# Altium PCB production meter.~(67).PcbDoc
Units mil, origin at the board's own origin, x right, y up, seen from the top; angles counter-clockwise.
Board outline 4724.41 x 1338.58 mil, 2 copper layers (Top Layer, Bottom Layer); 57 components, 53 nets, 214 pads, 21 vias.
Unrouted connection lines stored in the file: 27.
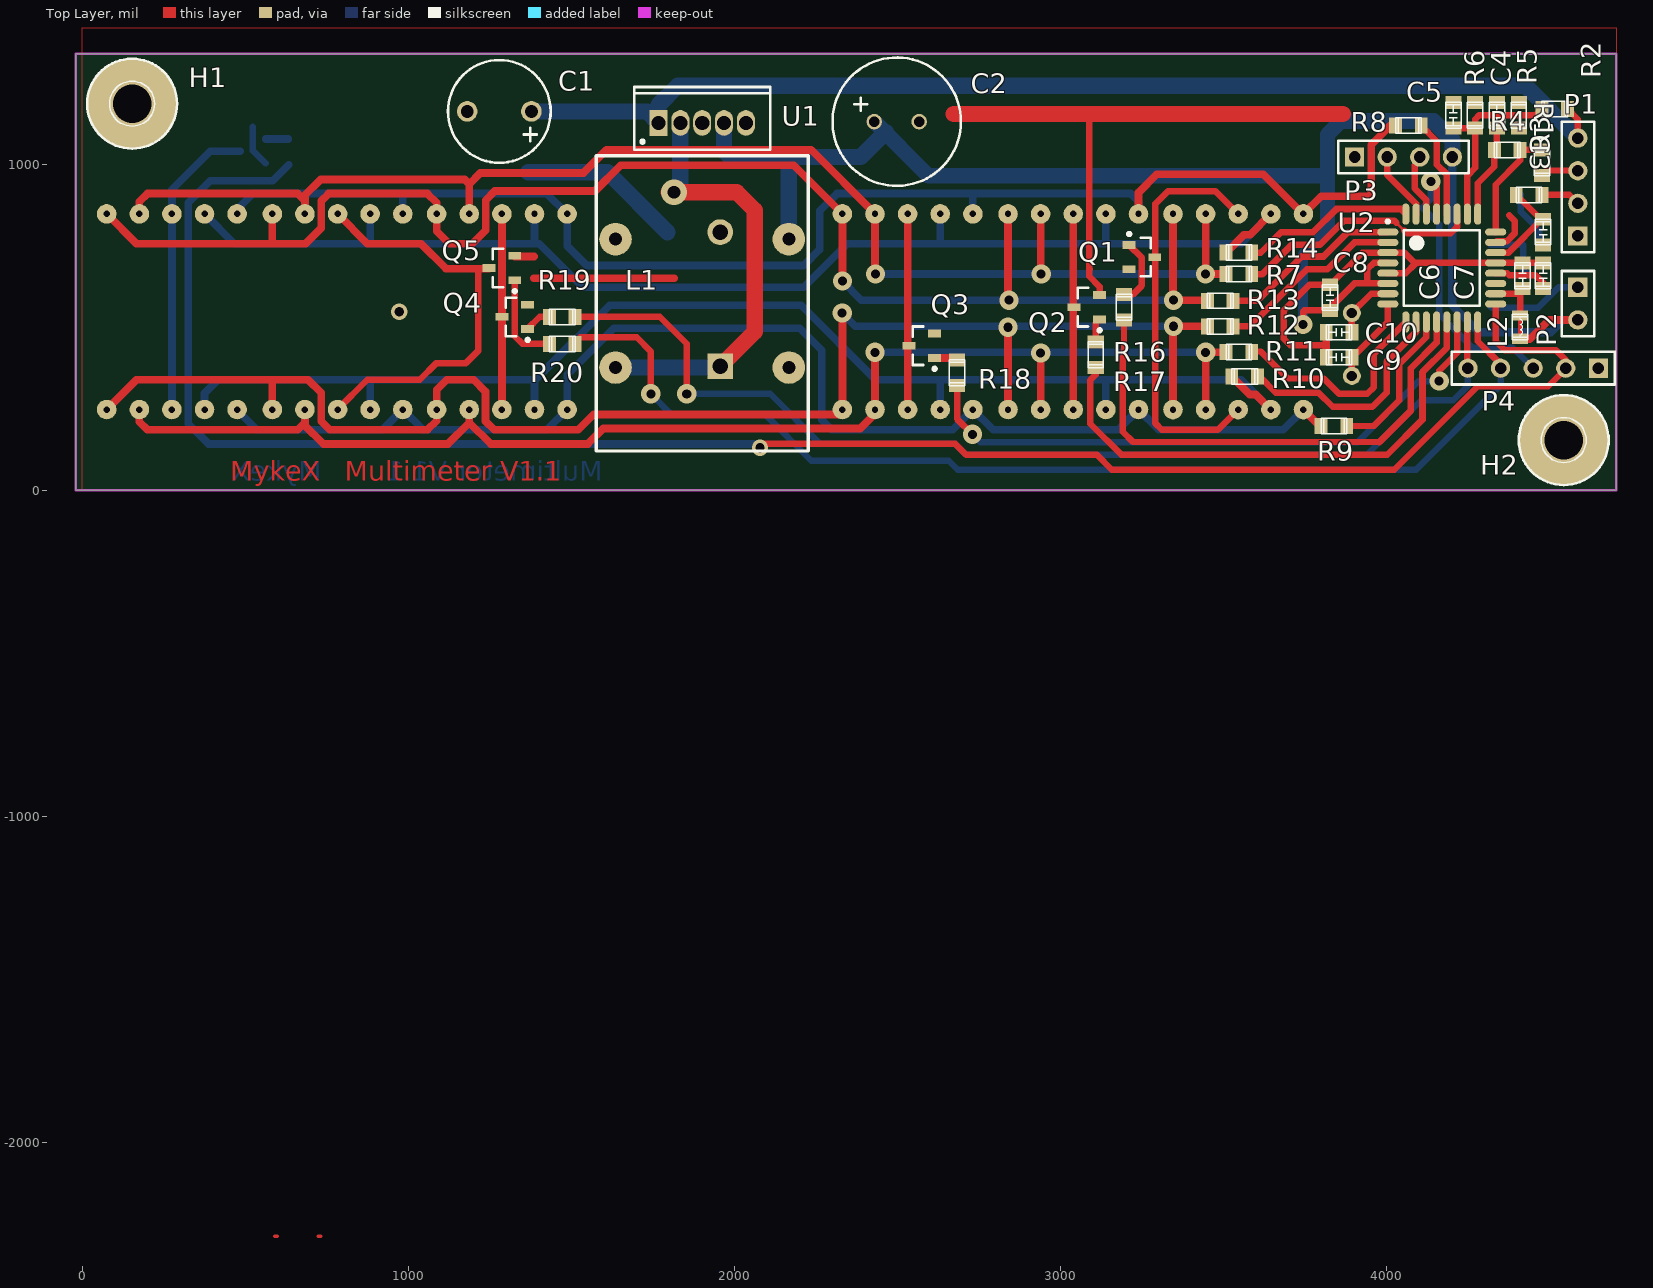
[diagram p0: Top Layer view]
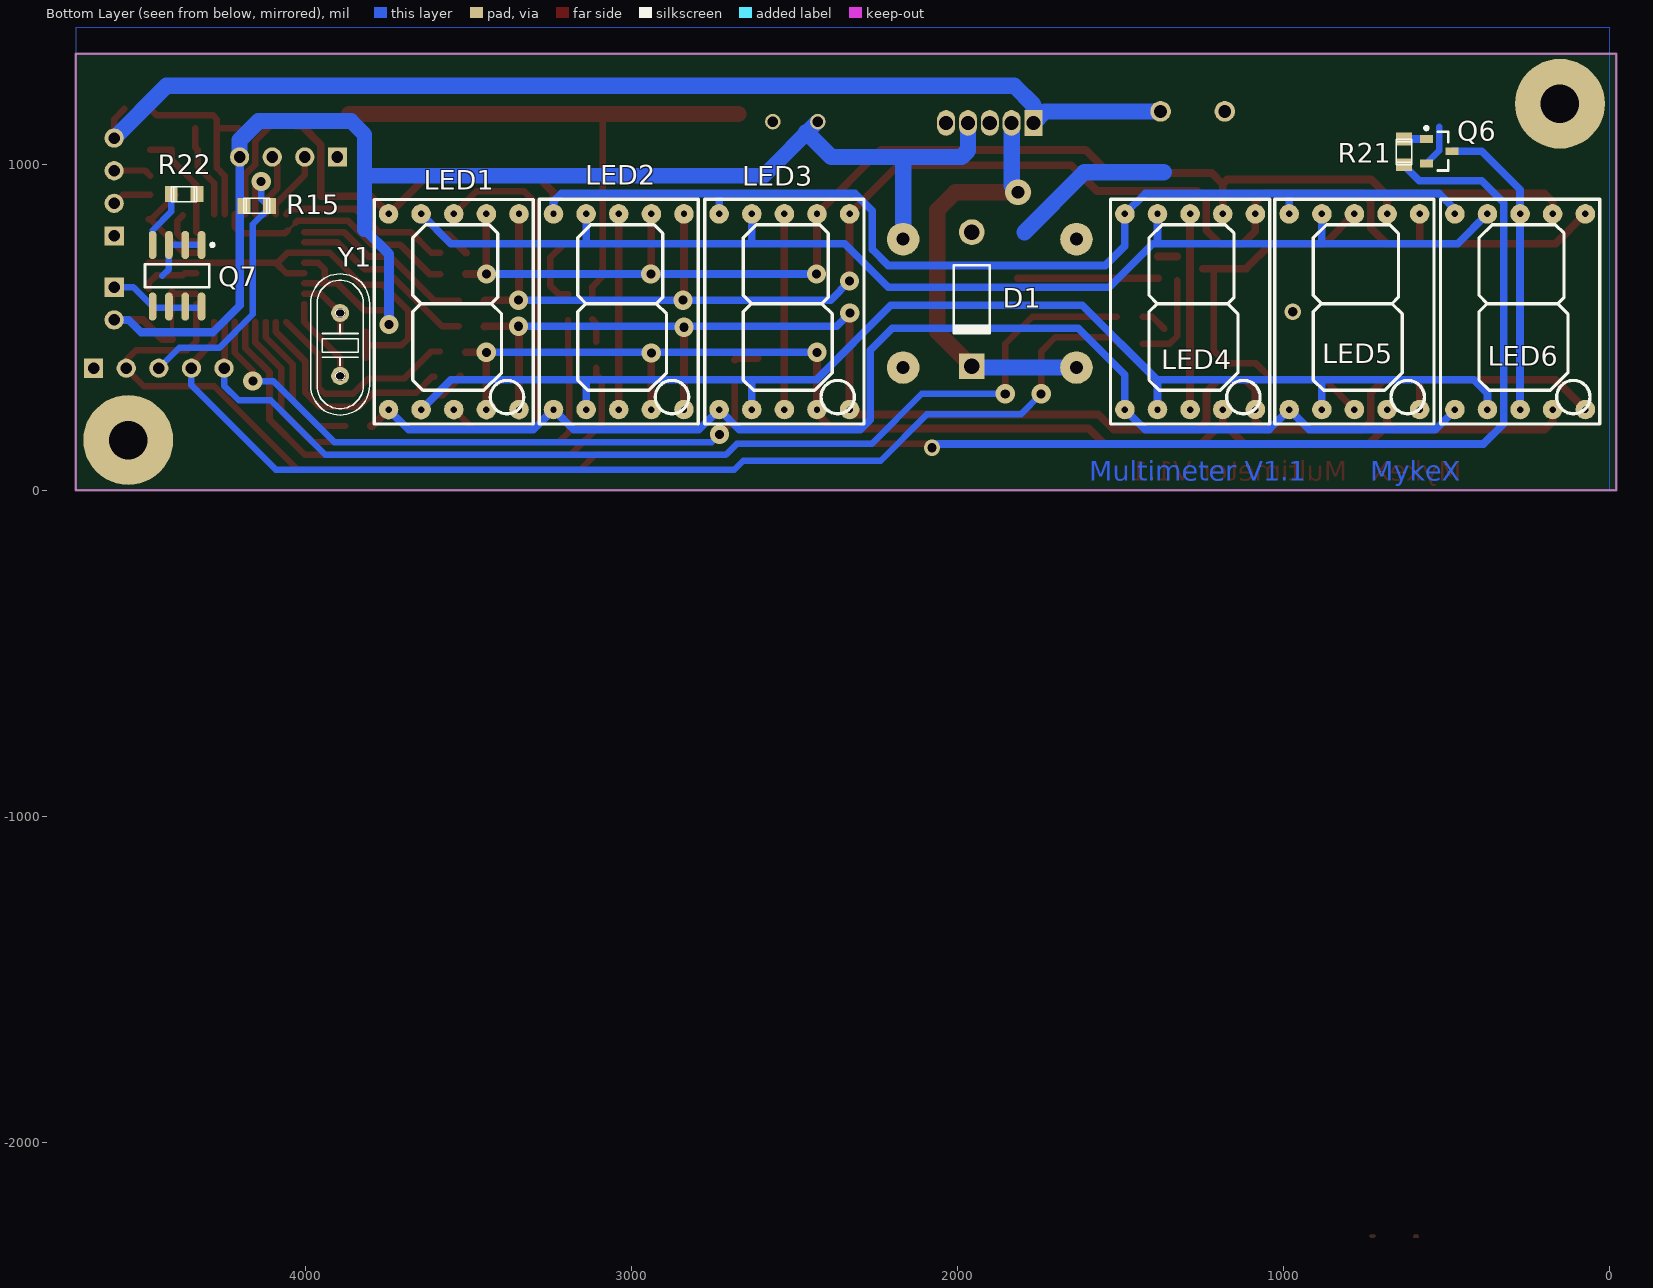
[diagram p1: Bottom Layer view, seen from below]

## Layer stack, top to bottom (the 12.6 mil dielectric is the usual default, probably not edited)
Top Layer: signal copper 1.4
Dielectric: dielectric 12.6, FR-4, Dk 4.8
Bottom Layer: signal copper 1.4

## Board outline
-19.69,0 -19.69,1338.58 4704.72,1338.58 4704.72,0

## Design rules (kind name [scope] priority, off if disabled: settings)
Clearance PolygonGND [InPolygon] p1: gap=19.68
Clearance [All] p2: gap=7.87
ComponentClearance [All] p1: gap=3.94 collisioncheckmode=3 verticalgap=0 showdistances=FALSE
HoleSize [All] p1: absolutevalues=TRUE maxlimit=196.85 minlimit=1 maxpercent=80.000 minpercent=20.000
MinimumSolderMaskSliver [All] p1: minsoldermaskwidth=0
PlaneClearance [All] p1: clearance=39.37
PlaneClearance PlaneClearance_1 [All] p2: clearance=31.5
PolygonConnect [All] p1: connectstyle=Relief reliefconductorwidth=39.37 reliefentries=4 polygonreliefangle="90 Angle"
RoutingVias [All] p1: holewidth=28 width=50 viastyle="Through Hole" minholewidth=28 minwidth=50 maxholewidth=78.74 maxwidth=78.74
SilkToSilkClearance [All] p1: silktosilkclearance=0
SilkscreenOverComponentPads [All] p1: minsilkscreentomaskgap=0
SolderMaskExpansion [All] p1: expansion=4
Width [All] p1: maxlimit=78.74 minlimit=7.87 preferedwidth=19.68
22 further rules are at their usual default settings.

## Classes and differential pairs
net class PB[5..0]: PB0 PB1 PB2 PB3 PB4 PB5
net class PD[7..0]: PD0 PD1 PD2 PD3 PD4 PD5 PD6 PD7

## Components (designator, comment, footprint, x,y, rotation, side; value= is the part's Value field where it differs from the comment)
C1 "100uFx50V" CEd8p5 1377.95,1161.42 r180 top
C2 "1000uFx3.6V" CEd10p3.5 2429.13,1129.92 r0 top
C3 "0.1uF" C0805\2P 4480.31,826.77 r270 top
C4 "0.1uF" C0805\2P 4338.58,1114.17 r90 top
C5 "0.1uF" C0805\2P 4204.72,1114.17 r90 top
C6 "0.1uF" C0805\2P 4417.32,692.91 r270 top
C7 "0.1uF" C0805\2P 4480.31,692.91 r270 top
C8 "0.1uF" C0805\2P 3826.77,555.12 r90 top
C9 "22pF" C0805\2P 3818.9,407.56 r0 top
C10 "22pF" C0805\2P 3818.9,484.25 r0 top
D1 "Diode 11DQ03" DIO10.46-5.3x2.8 1956.69,585.43 r270 bottom
H1 "Hole_3mm" F3.5X7.5_Met_NH 153.54,1185.04 r0 top
H2 "Hole_3mm" F3.5X7.5_Met_NH 4543.31,153.54 r0 top
L1 "Inductor 330uH 1A" "Inductor footprint" 2167.32,129.92 r90 top
L2 "47uH" LL0805\2P 4409.45,535.43 r270 top
LED1 "SA52-11GWA" SA52-11GWA 3789.33,202.68 r180 bottom
LED2 "SA52-11GWA" SA52-11GWA 3283.46,202.76 r180 bottom
LED3 "SA52-11GWA" SA52-11GWA 2775.59,202.76 r180 bottom
LED4 "SA52-11GWA" SA52-11GWA 1531.5,202.76 r180 bottom
LED5 "SA52-11GWA" SA52-11GWA 1027.56,202.76 r180 bottom
LED6 "SA52-11GWA" SA52-11GWA 519.69,202.76 r180 bottom
P1 "Header 4" HDR1X4 4586.61,779.53 r90 top
P2 "Fan" HDR1X2 4586.61,622.05 r270 top
P3 "UART" HDR1X4 3901.97,1021.65 r0 top
P4 "ISP Header" HDR1X5 4649.61,374.02 r180 top
Q1 "BC847C" SOT23_L 3250,714.57 r0 top
Q2 "BC847C" SOT23_L 3080.71,561.02 r180 top
Q3 "BC847C" SOT23_L 2574.8,442.91 r180 top
Q4 "BC847C" SOT23_L 1326.77,531.5 r180 top
Q5 "BC847C" SOT23_L 1287.4,681.1 r180 top
Q6 "BC847C" SOT23_L 523.62,1039.37 r180 bottom
Q7 "IRF7811AV" SO-8_N 4393.7,657.48 r270 bottom
R1 "1k" R0805\2P 4476.38,1039.37 r270 top
R2 "1k" R0805\2P 4480.31,1169.29 r0 top
R3 "1k" R0805\2P 4401.57,905.51 r0 top
R4 "1k" R0805\2P 4334.65,1043.31 r0 top
R5 "1k" R0805\2P 4405.51,1185.04 r270 top
R6 "1k" R0805\2P 4271.65,1185.04 r270 top
R7 "180" R0805\2P 3582.68,662.68 r180 top
R8 "180" R0805\2P 4102.36,1118.11 r180 top
R9 "180" R0805\2P 3874.02,196.85 r180 top
R10 "180" R0805\2P 3600.39,348.43 r180 top
R11 "180" R0805\2P 3582.68,423.23 r180 top
R12 "180" R0805\2P 3525.59,501.97 r180 top
R13 "180" R0805\2P 3525.59,580.71 r180 top
R14 "180" R0805\2P 3582.68,728.35 r180 top
R15 "10k" R0805\2P 4185.04,872.05 r180 bottom
R16 "1k" R0805\2P 3194.88,525.59 r90 top
R17 "1k" R0805\2P 3108.27,379.92 r90 top
R18 "1k" R0805\2P 2683.07,324.8 r90 top
R19 "1k" R0805\2P 1507.87,531.5 r180 top
R20 "1k" R0805\2P 1507.87,448.82 r180 top
R21 "1k" R0805\2P 631.89,1001.97 r90 bottom
R22 "1k" R0805\2P 4336.61,907.48 r0 bottom
U1 "LM2575T-5.0" T05A 1901.57,1125.98 r0 top
U2 "ATmega8-16AI" 32A_N 4169.29,681.1 r0 top
Y1 "XTAL" XTAL_AXIAL_L11W4.6P4.9 3893.7,543.31 r270 bottom

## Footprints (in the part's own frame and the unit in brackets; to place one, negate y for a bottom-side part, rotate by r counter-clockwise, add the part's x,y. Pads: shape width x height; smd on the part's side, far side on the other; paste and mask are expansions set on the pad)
32A_N [mm] "Thin QFP, 32-Leads, Body 7x7mm, Pitch 0.8mm, IPC Medium Density"
  oval 1.65x0.55 smd: 1(-4.2,2.8) 2(-4.2,2) 3(-4.2,1.2) 4(-4.2,0.4) 5(-4.2,-0.4) 6(-4.2,-1.2) 7(-4.2,-2) 8(-4.2,-2.8) 17(4.2,-2.8) 18(4.2,-2) 19(4.2,-1.2) 20(4.2,-0.4) 21(4.2,0.4) 22(4.2,1.2) 23(4.2,2) 24(4.2,2.8)
  oval 0.55x1.65 smd: 9(-2.8,-4.2) 10(-2,-4.2) 11(-1.2,-4.2) 12(-0.4,-4.2) 13(0.4,-4.2) 14(1.2,-4.2) 15(2,-4.2) 16(2.8,-4.2) 25(2.8,4.2) 26(2,4.2) 27(1.2,4.2) 28(0.4,4.2) 29(-0.4,4.2) 30(-1.2,4.2) 31(-2,4.2) 32(-2.8,4.2)
  silkscreen extent -4.32,-2.95 2.95,3.75, body extent -3.5,-3.5 3.5,3.5, height 1.2
C0805\2P [mm]
  rect 1x1.25 smd: 1(-0.1,0) 2(1.9,0)
  silkscreen extent -0.1,-0.6 1.9,0.6
CEd8p5 [mm] "Electrolytic capacitor, Diameter 8mm, Pitch 5mm"
  round 1.6 hole 1: 1(0,0) 2(5,0)
  silkscreen extent -1.5,-4 6.5,4
CEd10p3.5 [mm] "Electrolytic capacitor, Diameter 10mm, Pitch 3.5mm"
  round 1.2 hole 0.8: 1(0,0) 2(3.5,0)
  silkscreen extent -3.25,-5 6.75,5
DIO10.46-5.3x2.8 [mm] "Diode, Axial; Body 5.2 x 2.7 mm (LxDia. max), Lead Dia. 0.86 mm (max)"
  round 2 hole 1.2: 1(-5.23,0)
  rect 2x2 hole 1.2: 2(5.23,0)
  silkscreen extent -2.65,-1.41 2.75,1.4
F3.5X7.5_Met_NH [mm]
  round 7 hole 3: 0(0,0)
  silkscreen extent -3.5,-3.5 3.5,3.5
HDR1X2 [mm] "Connector; Header; 2 Position"
  rect 1.5x1.5 hole 0.9: 1(0,0)
  round 1.5 hole 0.9: 2(2.54,0)
  silkscreen extent -1.27,-1.27 3.81,1.27
HDR1X4 [mm] "Connector; Header; 4 Position"
  rect 1.5x1.5 hole 0.9: 1(0,0)
  round 1.5 hole 0.9: 2(2.54,0) 3(5.08,0) 4(7.62,0)
  silkscreen extent -1.27,-1.27 8.89,1.27
HDR1X5 [mm] "Connector; Header; 5 Position"
  rect 1.5x1.5 hole 0.9: 1(0,0)
  round 1.5 hole 0.9: 2(2.54,0) 3(5.08,0) 4(7.62,0) 5(10.16,0)
  silkscreen extent -1.27,-1.27 11.43,1.27
"Inductor footprint" [mm]
  round 2.54 hole 1: 0(6.25,0) 0(16.25,13.5) 1(6.25,13.5) 2(16.25,0)
  silkscreen extent -0.25,-1.5 22.75,15
LL0805\2P [mm]
  rect 0.8x1.25 smd: 1(0,0) 2(1.8,0)
  silkscreen extent -0.1,-0.6 1.9,0.6
R0805\2P [mm]
  rect 1x1.25 smd: 1(-0.1,0) 2(1.9,0)
  silkscreen extent -0.1,-0.6 1.9,0.6
SA52-11GWA [mm]
  round 1.524 hole 0.5: 1(1.12,1.13) 2(3.66,1.13) 3(6.2,1.13) 4(8.74,1.13) 5(11.28,1.13) 6(11.28,16.37) 7(8.74,16.37) 8(6.2,16.37) 9(3.66,16.37) 10(1.12,16.37)
  silkscreen extent 0,0 12.4,17.5
SO-8_N [mm] "SOIC, 8-Leads, Body 4.9x3.9mm, Pitch 1.27mm, IPC Medium Density"
  oval 2.2x0.6 smd: 1(-2.4,1.905) 2(-2.4,0.635) 3(-2.4,-0.635) 4(-2.4,-1.905) 5(2.4,-1.905) 6(2.4,-0.635) 7(2.4,0.635) 8(2.4,1.905)
  silkscreen extent -2.52,-2.5 0.9,2.88, body extent -1.95,-2.45 1.95,2.45, height 1.75
SOT23_L [mm] "SOT23, 3-Leads, Body 2.9x1.3mm, Pitch 0.95mm, Lead Span 2.3mm, IPC High Density"
  rect 1x0.6 smd: 1(-1,0.95) 2(-1,-0.95) 3(1,0)
  silkscreen extent -1.12,-1.5 0.7,1.92, body extent -0.7,-1.5 0.7,1.5, height 1.1
T05A [mm] "TO, Thru-Hole, Vertical, Heatsink Mounted; 5 In-Line Leads; Pitch 1.70 mm"
  rect 1.4x2 hole 1.1: 1(-3.4,0)
  oval 1.4x2 hole 1.1: 2(-1.7,0) 3(0,0) 4(1.7,0) 5(3.4,0)
  silkscreen extent -5.3,-2.1 5.3,2.8
XTAL_AXIAL_L11W4.6P4.9 [mm] "Quartz Crystal"
  round 1.4 hole 0.8: 1(0,0) 2(4.9,0)
  silkscreen extent -3.05,-2.3 7.95,2.3

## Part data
C1 C2: library part Cap_Elect, "Electrolytic capacitor"
C3 C4 C5 C6 C7 C8 C9 C10: library part Cap_Cer, "Capacitor ceramic"
D1: "Schottky Rectifier"
L1: library part "Inductor 330uH 1A_1"
L2: library part Inductor
P1: "Header, 4-Pin"
P2: library part "Header 2", "Header, 2-Pin"
P3: library part "Header 4", "Header, 4-Pin"
P4: library part "Header 5", "Header, 5-Pin"
Q1 Q2 Q3 Q4 Q5 Q6: "NPN General-purpose Transistor"
Q7: "HEXFET Power MOSFET"
R1 R2 R3 R4 R5 R6 R7 R8 R9 R10 R11 R12 R13 R14 R15 R16 R17 R18 R19 R20 R21 R22: library part Res, "Resistor"
U1: "SIMPLE SWITCHER 1A Step-Down Voltage Regulator"
U2: "8-Bit AVR Microcontroller with 8K Bytes of In-System Programmable Flash Memory"
Y1: "Quartz Crystal"

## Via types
v1: diameter 59.06, hole 28, Top Layer to Bottom Layer, 18 vias
v2: diameter 50, hole 28, Top Layer to Bottom Layer, 2 vias
v3: diameter 78.74, hole 39.37, Top Layer to Bottom Layer, 1 vias

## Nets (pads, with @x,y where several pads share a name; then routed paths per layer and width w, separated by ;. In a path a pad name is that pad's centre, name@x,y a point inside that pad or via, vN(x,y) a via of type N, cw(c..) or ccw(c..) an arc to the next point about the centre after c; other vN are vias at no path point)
GND: C1.2 C2.2 C3.2 C4.2 C5.2 C6.1 C7.1 C8.2 C9.1 C10.1 D1.1 H1.0 H2.0 P1.1 P3.1 P4.1 Q1.2 Q2.2 Q3.2 Q4.2 Q5.2 Q6.2 Q7.1 Q7.2 Q7.3 R5.1 R6.1 U1.3 U1.5 U2.3 U2.5 U2.21 | length 4357.8
  Top Layer w19.68: 3088.58,1153.54 3088.58,679.13 ; 3090.55,677.16 3088.58,679.13 ; Q2.2 3120.08,624.02 3088.58,655.51 3088.58,679.13 ; 3814.96,444.88 3704.72,444.88 3685.04,464.57 3685.04,551.18 3763.78,629.92 C8.2@3818.9,629.92 ; C8.2@3827.46,629.92 3925.89,728.35 U2.3 4055.12,728.35 4086.61,696.85 U2.21 C6.1 C7.1 ; U2.5 4059.06,665.35 4088.58,694.88
  Top Layer w23.62: Q5.2@1326.77,716.54 1385.83,716.54 ; 1385.83,649.61 1814.96,649.61 ; C9.1 3814.96,444.88 C10.1
  Top Layer w50: 2673.23,1153.54 3088.58,1153.54 3866.14,1153.54
  Bottom Layer w19.68: 523.62,1114.17 523.62,1041.34 Q6.2 ; Q7.1 Q7.2 Q7.3 4418.7,677.76 4438.98,657.48
  Bottom Layer w50: 1368.11,974.41 1612.2,974.41 1795.28,791.34
  other v2: 972.44,547.24
NetC1_1: C1.1 P1.4 R2.2 U1.1 | length 3473
  Top Layer w19.68: R2.2 4586.61,1137.8 P1.4 P1.4@4585.83,1079.53
  Bottom Layer w50: C1.1 1732.28,1161.42 U1.1 1767.72,1181.1 1826.77,1240.16 4425.98,1240.16 P1.4
NetC3_1: C3.1 R3.1 U2.22 | length 297.8
  Top Layer w19.68: U2.22 4374.02,728.35 C3.1@4476.38,830.71 ; R3.1 4472.44,830.71 C3.1@4476.38,830.71 ; C3.1 C3.1@4476.38,830.71
NetC4_1: C4.1 R4.1 R5.2 U2.25 | length 288.2
  Top Layer w19.68: U2.25 4279.53,940.95 4330.71,992.13 R4.1 4338.58,1051.18 C4.1
NetC5_1: C5.1 R2.1 R6.2 U2.26 | length 585.8
  Top Layer w19.68: C5.1 R6.2 ; U2.26 4248.03,964.57 4271.65,988.19 R6.2 ; R2.1 4456.69,1149.61 4283.46,1149.61 4271.65,1137.8 R6.2
NetC7_2: C7.2 U2.20 | length 175.6
  Top Layer w19.68: U2.20 4370.08,665.35 4375.98,659.45 4456.69,659.45 4480.31,635.83 C7.2
NetC9_2: C9.2 U2.8 Y1.2 | length 266.1
  Top Layer w19.68: Y1.2 3893.7,405.51 4003.94,515.75 U2.8
NetC10_2: C10.2 U2.7 Y1.1 | length 193.8
  Top Layer w19.68: C10.2 Y1.1 3952.76,602.36 U2.7
NetD1_2: D1.2 L1.1 U1.2 | length 1351
  Top Layer w50: v3@1799.21,913.39 2007.87,913.39 2062.99,858.27 2062.99,485.83 D1.2
  Bottom Layer w50: L1.1 D1.2@1956.69,375.98 ; v3(1814.96,913.39) 1834.65,933.07 U1.2
NetLED1_3: LED1.3 LED1.8 Q1.3 | length 1263.1
  Top Layer w20: LED1.8 3475.08,917.32 3330.71,917.32 3291.34,877.95 3291.34,204.72 3311.02,185.04 3483.11,185.04 LED1.3 LED1.3@3547.24,245.16
NetLED2_3: LED2.3 LED2.8 Q2.3 | length 600
  Top Layer w23.62: LED2.3 LED2.8
NetLED3_3: LED3.3 LED3.8 Q3.3 | length 600
  Top Layer w23.62: LED3.3 LED3.8
NetLED4_3: LED4.3 LED4.8 Q4.3 | length 600
  Top Layer w23.62: LED4.3 LED4.8
NetLED5_3: LED5.3 LED5.8 Q5.3 | length 1324.8
  Top Layer w20: LED5.3 874.8,338.58 1035.43,338.58 1086.61,389.76 1177.17,389.76 1215.36,427.95 1215.36,679.13 Q5.3@1248.03,679.13
  Top Layer w23.62: LED5.8 874.8,755.91 1039.37,755.91 1116.14,679.13 Q5.3@1248.03,679.13
NetLED6_3: LED6.3 LED6.8 Q6.3 | length 931.6
  Bottom Layer w23.62: LED6.3 LED6.8 275.59,921.26 393.7,1039.37 Q6.3
NetP1_2: P1.2 R3.2 | length 121
  Top Layer w19.68: R3.2 4560.63,905.51 P1.2
NetP1_3: P1.3 R1.2 | length 117.1
  Top Layer w19.68: R1.2 4492.13,980.31 4585.83,980.31 P1.3
NetP2_1: P2.1 Q7.5 Q7.6 Q7.7 Q7.8 | length 301.2
  Bottom Layer w19.68: Q7.8 4322.64,559.06 4418.7,559.06 Q7.5@4464.57,559.06 ; Q7.5@4468.5,562.99 Q7.5@4464.57,559.06 ; P2.1 4527.56,622.05 Q7.5@4464.57,559.06
NetP3_2: P3.2 U2.31 | length 202.2
  Top Layer w19.68: P3.2@4001.57,1011.81 4001.57,966.93 4090.55,877.95 U2.31
NetP3_3: P3.3 U2.30 | length 186.2
  Top Layer w19.68: P3.3@4101.57,1011.81 4086.61,996.85 4086.61,925.2 4122.05,889.76 U2.30
NetP4_3: P4.3 R15.2 U2.29 | length 878.6
  Top Layer w19.68: U2.29 v1@4153.54,929.13
  Bottom Layer w19.68: v1(4135.83,946.85) 4135.83,891.73 4110.24,866.14 4161.42,814.96 4161.42,539.37 4263.78,437.01 4386.61,437.01 P4.3
NetQ1_1: Q1.1 R16.2 | length 206.9
  Top Layer w20: R16.2 3222.44,600.39 3250,627.95 3250,712.6 Q1.1
NetQ2_1: Q2.1 R17.2 | length 73.8
  Top Layer w20: R17.2 3108.27,511.81 Q2.1
NetQ3_1: Q3.1 R18.2 | length 71.3
  Top Layer w23.62: Q3.1 2677.17,405.51 R18.2
NetQ4_1: Q4.1 R19.2 | length 82.4
  Top Layer w19.68: Q4.1 1403.54,531.5 R19.2
NetQ5_1: Q5.1 R20.2 | length 287.3
  Top Layer w19.68: Q5.1 1326.77,472.44 1350.39,448.82 R20.2
NetQ6_1: Q6.1 R21.2 | length 68.9
  Bottom Layer w23.62: Q6.1 R21.2
NetQ7_4: Q7.4 R22.2 | length 179.2
  Bottom Layer w19.68: R22.2 4411.42,854.33 4468.7,797.05 Q7.4
NetR1_1: R1.1 R4.2 U2.24 | length 349.9
  Top Layer w19.68: U2.24 4334.65,937.01 4409.45,1011.81 R4.2 R1.1
NetR7_1: R7.1 U2.27 | length 755.1
  Top Layer w7.87: 4035.43,814.96 4054.13,796.26
  Top Layer w19.68: 4054.13,796.26 4062.99,787.4 4196.85,787.4 4216.54,807.09 U2.27
  Top Layer w20: R7.1@3586.61,661.42 3618.11,661.42 3708.66,751.97 3795.28,751.97 3870.08,826.77 4023.62,826.77 4030.35,820.04
NetR8_1: R8.1 U2.28 | length 304.3
  Top Layer w20: R8.1 4154.17,1070.24 4154.17,998.58 4185.04,967.71 U2.28
NetR9_1: R9.1 U2.11 | length 468.4
  Top Layer w19.68: R9.1 3960.63,196.85 4039.37,275.59 4039.37,385.83 4122.05,468.5 U2.11
NetR10_1: R10.1 U2.10 | length 706
  Top Layer w19.68: R10.1 3611.46,348.43 3660.67,299.21 3791.34,299.21 3834.65,255.91 3956.69,255.91 4000,299.21 4000,394.67 4090.55,485.22 U2.10
NetR11_1: R11.1 U2.9 | length 675.6
  Top Layer w19.68: R11.1@3588.58,425.2 3614.17,425.2 3627.95,411.42 3696.85,342.52 3807.09,342.52 3854.33,295.28 3940.94,295.28 3960.63,314.96 3960.63,417.32 U2.9
NetR12_1: R12.1 U2.2 | length 581.2
  Top Layer w20: R12.1 3580.71,501.97 3755.91,677.17 3818.9,677.17 3901.57,759.84 U2.2
NetR13_1: R13.1 U2.1 | length 561.7
  Top Layer w20: R13.1 3604.33,580.71 3740.16,716.54 3807.09,716.54 3881.89,791.34 U2.1
NetR14_1: R14.1 U2.32 | length 534.4
  Top Layer w20: R14.1 3614.17,728.35 3677.17,791.34 3775.59,791.34 3846.46,862.2 4043.31,862.2 U2.32
NetR22_1: R22.1 U2.23 | length 132.4
  Top Layer w19.68: U2.23 4337.6,762.8 4368.12,762.8 4393.7,788.37 4393.7,824.8 4375.98,842.52
PB0: R16.1 U2.12 | length 1585.3
  Top Layer w19.68: R16.1 3194.88,411.42 3190.94,407.48 3190.94,179.13 3222.44,147.64 3978.35,147.64
  Top Layer w20: 3978.35,147.64 4074.8,244.09 4074.8,374.02 4153.54,452.76 U2.12
PB1: R17.1 U2.13 | length 1613.9
  Top Layer w20: 3092.52,338.58 3091.5,337.56 ; R17.1 3108.27,354.33 3091.5,337.56 ; U2.13 4185.04,437.01 4110.24,362.2 4110.24,216.54 4001.97,108.27 3187.01,108.27 3091.5,203.78 3091.5,337.56
PB2: R18.1 U2.14 | length 1895.4
  Top Layer w20: R18.1@2683.07,324.8 2683.07,218.5 v1(2730.31,171.26) ; v1(4161.42,334.65) 4161.42,366.14 4216.54,421.26 U2.14
  Bottom Layer w20: v1(2730.31,171.26) 2753.94,147.64 3911.42,147.64 4098.43,334.65 v1(4161.42,334.65)
PB3: P4.5 R19.1 U2.15 | length 3286.2
  Top Layer w19.68: R19.1 1771.65,531.5 1854.33,448.82 v1(1854.33,295.28) ; P4.5@4248.03,374.02 U2.15
  Bottom Layer w19.68: v1(1854.33,295.28) 2110.24,295.28 2263.78,141.73 2677.17,141.73 2710.63,108.27 3938.98,108.27 4106.3,275.59 4204.72,275.59 4249.61,320.47 P4.5
PB4: P4.4 R20.1 U2.16 | length 3442.9
  Top Layer w19.68: R20.1@1507.87,448.82 1527.56,468.5 1700.79,468.5 1744.09,425.2 v1(1744.09,295.28) ; U2.16 4279.53,456.69 4349.61,386.61 P4.4@4349.61,355.12
  Bottom Layer w19.68: v1(1744.09,295.28) 1807.09,232.28 2094.49,232.28 2236.22,90.55 2657.48,90.55 2685.04,62.99 4090.55,62.99 4349.61,322.05 P4.4
PB5: P4.2 R21.1 U2.17 | length 5826.3
  Top Layer w19.68: v2@2082.68,137.8 2086.61,141.73 2677.17,141.73 2710.63,108.27 3112.2,108.27 3157.48,62.99 4023.62,62.99 4279.53,318.9 4496.06,318.9 4549.61,372.44 4549.61,399.21 4519.68,429.13 4362.2,429.13 4334.65,456.69 U2.17
  Bottom Layer w23.62: R21.1@633.86,998.03 584.65,948.82 393.7,948.82 325.91,881.02 325.91,203.62 387.8,141.73 2066.93,141.73 v2(2078.74,129.92)
PD0: LED1.10 LED2.10 LED3.10 LED4.10 LED5.10 LED6.10 R8.2 | length 4411.1
  Top Layer w23.62: LED2.10 3239.37,912.6 3295.28,968.5 3622.05,968.5 3743.39,847.17 LED1.10 3799.65,901.57 3952.76,901.57 3952.76,1059.06 4011.81,1118.11 R8.2
  Bottom Layer w23.62: LED6.10 475.59,861.42 523.62,909.45 984.25,909.45 ; LED5.10 983.47,908.66 984.25,909.45 ; LED3.10 2731.5,908.66 ; LED2.10 3239.37,885.83 3215.75,909.45 2314.96,909.45 2261.81,856.3 2261.81,738.19 2212.6,688.98 1547.24,688.98 1487.4,748.82 LED4.10 1425.2,909.45 984.25,909.45
PD1: LED1.9 LED2.9 LED3.9 LED4.9 LED5.9 LED6.9 R14.2 | length 4001.8
  Top Layer w23.62: R14.2 3562.99,783.46 3581.54,783.46 LED1.9
  Bottom Layer w23.62: LED6.9 466.93,755.91 1401.57,755.91 1535.43,622.05 2212.6,622.05 2346.46,755.91 3553.98,755.91 LED1.9 ; 883.47,757.48 LED5.9 ; 1387.4,757.48 LED4.9 ; 2631.5,757.48 LED3.9 ; 3139.37,757.48 LED2.9
PD2: LED1.7 LED2.7 LED3.7 LED4.7 LED5.7 LED6.7 R7.2 | length 4235.3
  Top Layer w23.62: LED6.7 175.59,884.25 200.79,909.45 661.42,909.45 683.47,887.4 ; LED5.7 683.47,887.4 ; LED4.7 1187.4,938.58 ; v1@2431.5,665.04 LED3.7 2235.43,1043.31 1608.27,1043.31 1537.4,972.44 1221.26,972.44 1187.4,938.58 ; v1@2939.37,664.25 LED2.7 ; LED1.7 3445.24,662.68 R7.2 ; 683.47,887.4 683.47,903.94 732.28,952.76 1173.23,952.76 1187.4,938.58
  Bottom Layer w23.62: v1(2433.07,662.68) v1(2940.94,662.68) v1(3444.88,662.68)
PD3: LED1.6 LED2.6 LED3.6 LED4.6 LED5.6 LED6.6 R13.2 | length 4707.8
  Top Layer w23.62: LED6.6 166.93,755.91 583.47,755.91 ; LED5.6 583.47,755.91 ; v1@2330.71,641.73 2331.5,642.52 LED3.6 2182.68,996.06 1651.57,996.06 1572.83,917.32 1265.75,917.32 1237.72,889.29 1237.72,796.77 1196.85,755.91 1125.98,755.91 1087.4,794.49 LED4.6 1087.4,881.1 1059.06,909.45 755.91,909.45 733.15,886.69 733.15,804.02 685.04,755.91 583.47,755.91 ; v1@2838.58,582.68 2839.37,583.46 LED2.6 ; LED1.6 3345.24,583.9 v1(3346.46,582.68) 3448.82,582.68 R13.2
  Bottom Layer w23.62: v1@2330.71,641.73 2389.76,582.68 v1(2842.52,582.68) v1(3346.46,582.68)
  other v1: 2331.5,641.73
PD4: LED1.5 LED2.5 LED3.5 LED4.5 LED5.5 LED6.5 R12.2 | length 4713.9
  Top Layer w23.62: LED6.5 166.93,338.58 583.47,338.58 ; LED5.5 583.47,338.58 ; LED3.5@2331.5,232.28 1568.9,232.28 1521.65,185.04 1263.78,185.04 1237.09,211.73 1237.09,302.28 1200.79,338.58 1118.11,338.58 1087.4,307.87 LED4.5 1087.4,213.39 1059.05,185.04 759.84,185.04 733.15,211.73 733.15,298.35 692.91,338.58 583.47,338.58 ; LED3.5 v1@2331.5,553.54 ; LED2.5 v1(2839.37,499.53) ; LED1.5 3345.24,502.72 v1@3346.46,503.94 ; v1@3347.72,503.94 v1(3346.46,502.68) 3450.08,502.68 R12.2
  Bottom Layer w23.62: v1(2330.71,543.31) 2371.34,502.68 v1@2842.52,502.68 ; v1(2839.37,499.53) v1@2842.52,502.68 ; v1(3346.46,502.68) v1@2842.52,502.68
PD5: LED1.4 LED2.4 LED3.4 LED4.4 LED5.4 LED6.4 R11.2 | length 4128.3
  Top Layer w23.62: LED6.4 175.59,210.24 200.79,185.04 661.42,185.04 683.47,207.09 ; LED5.4 683.47,207.09 ; LED4.4 1187.4,207.09 ; v1@2431.5,422.68 LED3.4 2431.5,234.65 2385.83,188.98 1598.43,188.98 1551.18,141.73 1252.76,141.73 1187.4,207.09 ; LED2.4 v1(2939.37,420.31) ; LED1.4 v1@3445.24,421.62 ; v1@3446.3,422.68 R11.2@3507.87,422.68 ; 683.47,207.09 683.47,198.42 740.16,141.73 1122.05,141.73 1187.4,207.09
  Bottom Layer w23.62: v1@2431.65,422.68 v1(3445.24,422.68)
  other v1: 2431.1,422.68
PD6: LED1.2 LED2.2 LED3.2 LED4.2 LED5.2 LED6.2 R10.2 | length 4086.8
  Top Layer w23.62: R10.2 3580.71,293.31 3599.1,293.31 LED1.2
  Bottom Layer w23.62: LED6.2 375.59,296.85 417.32,338.58 885.83,338.58 ; LED5.2 883.47,336.22 885.83,338.58 ; 1385.83,338.58 885.83,338.58 ; LED4.2 1387.4,336.22 1618.11,566.93 2204.72,566.93 2433.07,338.58 2629.92,338.58 ; LED3.2 2631.5,337.01 2629.92,338.58 ; LED2.2 3139.37,336.22 ; LED1.2 3553.82,338.58 2629.92,338.58
PD7: LED1.1 LED2.1 LED3.1 LED4.1 LED5.1 LED6.1 R9.2 | length 3996.4
  Top Layer w23.62: LED1.1 3795.55,196.85 R9.2
  Bottom Layer w23.62: LED6.1 475.59,244.88 535.43,185.04 921.26,185.04 LED5.1 1045.67,185.04 1425.2,185.04 LED4.1 1487.4,353.54 1629.92,496.06 2200.79,496.06 2267.72,429.13 2267.72,216.54 2299.21,185.04 2669.29,185.04 LED3.1 2793.7,185.04 3177.17,185.04 LED2.1 3301.58,185.04 3683.11,185.04 LED1.1
VCC: C2.1 C6.2 C8.1 L1.2 L2.1 L2.2 P2.2 P3.4 R15.1 U1.4 U2.4 U2.6 U2.18 | length 5175.4
  Top Layer w11.81: L2.2@4409.45,468.5 L2.1@4409.45,539.37
  Top Layer w19.68: v1(3744.09,507.87) 3744.09,547.24 3748.03,551.18 3818.9,551.18 3901.57,633.86 U2.6 ; 3940.94,633.86 3940.94,677.17 3960.63,696.85 U2.4 ; U2.18 4401.57,602.36 4409.45,610.24 4409.45,547.24 L2.1@4417.32,539.37
  Top Layer w23.62: L2.2@4409.45,462.99 4439.37,462.99 4498.43,522.05 P2.2
  Bottom Layer w25: P3.4@4201.57,1011.81 4201.57,566.14 4283.46,484.25 4503.94,484.25 4541.73,522.05 P2.2
  Bottom Layer w31.5: v1(3744.09,507.87) 3744.09,724.41 3818.9,799.21
  Bottom Layer w47.24: C2.1 2594.49,964.57 3818.9,964.57 ; 3818.9,799.21 3818.9,1090.55 3860.24,1131.89
  Bottom Layer w50: U1.4 1968.5,1041.34 1988.19,1021.65 2167.32,1021.65 ; L1.2 2167.32,1021.65 ; 2464.57,1098.43 2387.8,1021.65 2167.32,1021.65 ; 3860.24,1131.89 4143.7,1131.89 4201.97,1073.62 P3.4
pads on no net: L1.0 U2.19
copper on no net: | length 15.7
  Top Layer w10: 590.55,-2287.4 598.43,-2287.4 ; 724.41,-2287.4 732.28,-2287.4

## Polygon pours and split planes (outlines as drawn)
GND on Top Layer "Bottom Layer-No Net" (solid, remove dead copper, shelved, pour order 1000): 0,0 0,1417.32 4704.72,1417.32 4704.72,0 0,0
GND on Bottom Layer "Bottom Layer-No Net" (solid, remove dead copper, shelved, pour order 1001): 0,0 0,1417.32 4704.72,1417.32 4704.72,0 0,0

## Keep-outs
Keep-Out Layer:
  the board outline again, w7.87

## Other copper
Top Layer:
  text "MykeX" at 454.34,29.53 h60
  text "Multimeter V1.1" at 805.12,29.53 h60
Bottom Layer:
  text "MykeX" at 734.25,29.53 h60
  text "Multimeter V1.1" at 1596.46,29.53 h60

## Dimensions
4704.72,1338.58 to -19.69,1338.58 on Mechanical 13
4704.72,1338.58 to 4704.72,0 on Mechanical 13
